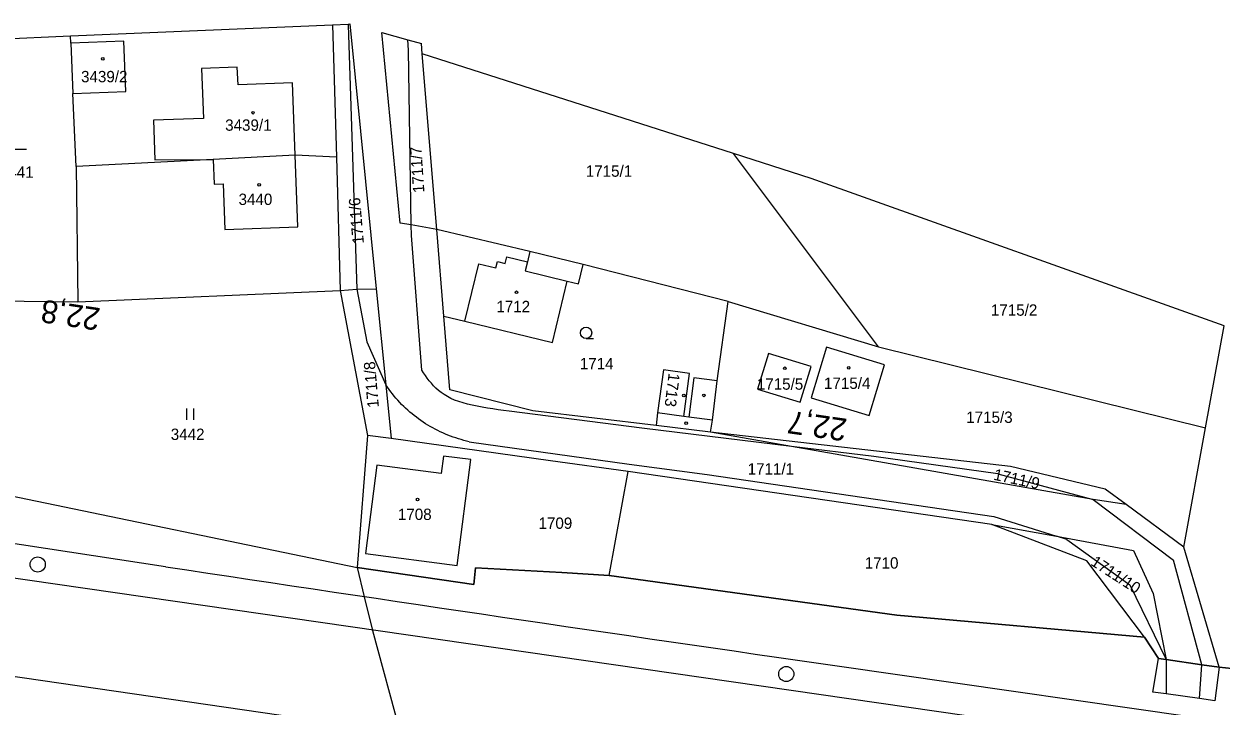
# Model space of a CAD drawing. Extents: x -757909 to -757266, y -1060303 to -1059942.
# Drawn here: x -757684 to -757525.7, y -1060142.5 to -1060052.3 of the extents above; entities that cross this region are included whole.
import ezdxf

# ---------------------------------------------------------------- set-up
doc = ezdxf.new("R2010")
doc.units = 0
for name, color, linetype in [('_hektaky', 7, 'Continuous'), ('_SO 102 hektometry', 7, 'Continuous'), ('Vrstva 1', 7, 'Continuous'), ('Vrstva 53', 7, 'Continuous'), ('Vrstva 55', 7, 'Continuous'), ('Vrstva 56', 7, 'Continuous'), ('Vrstva 57', 7, 'Continuous'), ('Vrstva 58', 7, 'Continuous'), ('Vrstva 59', 7, 'Continuous')]:
    doc.layers.add(name, color=color, linetype=linetype)

msp = doc.modelspace()

# ---------------------------------------------------------------- linework, layer by layer
at = {"layer": '_SO 102 hektometry'}
for centre in [(-757682.17, -1060123.76), (-757583.22, -1060138.24)]:
    msp.add_circle(centre, 1, dxfattribs=at)
at = {"layer": 'Vrstva 1'}
for p, q in [((-757429.32, -1060162.53), (-757720.62, -1060120.47)), ((-757665.26, -1060124.05), (-757689.98, -1060120.32)), ((-757576.18, -1060137.2), (-757470.2, -1060152.45))]:
    msp.add_line(p, q, dxfattribs=at)
msp.add_arc((-755796.09, -1047764.6), 12500, 261.400126, 261.812855, dxfattribs=at)
at = {"layer": 'Vrstva 53'}
for points in [[(-757852.31, -1060089.26), (-757789.66, -1060098.89), (-757785.7, -1060099.48), (-757730.83, -1060107.66), (-757729.12, -1060107.89), (-757699.16, -1060111.9), (-757687.19, -1060114.38), (-757639.93, -1060124.17), (-757624.54, -1060126.42), (-757624.32, -1060124.22), (-757612.89, -1060124.84), (-757606.63, -1060125.23), (-757568.62, -1060130.44), (-757535.86, -1060133.35), (-757534.03, -1060136.19), (-757533.01, -1060136.32), (-757528.28, -1060137.03), (-757525.99, -1060137.35), (-757523.49, -1060137.59)], [(-757328.56, -1060183.46), (-757338.29, -1060184.85), (-757361.91, -1060181.63), (-757443.58, -1060171.99), (-757470.38, -1060167.04), (-757513.1, -1060164.5), (-757526.21, -1060162.71), (-757533.6, -1060161.43), (-757535.01, -1060161.18), (-757542.9, -1060160.49), (-757543.88, -1060160.4), (-757632.1, -1060146.3), (-757634.26, -1060145.96), (-757635.44, -1060145.86), (-757686.64, -1060138.39), (-757693.18, -1060137.43), (-757732.62, -1060131.67), (-757793.56, -1060122.78), (-757866, -1060118.97)]]:
    msp.add_lwpolyline(points, dxfattribs=at)
at = {"layer": 'Vrstva 55'}
for p, q in [((-757677.84, -1060053.89), (-757643.18, -1060052.41)), ((-757643.18, -1060052.41), (-757642.66, -1060069.92)), ((-757643.18, -1060052.41), (-757642.66, -1060069.92)), ((-757640.91, -1060052.31), (-757637.42, -1060087.32)), ((-757688.39, -1060054.34), (-757677.84, -1060053.89)), ((-757677.8, -1060054.85), (-757677.84, -1060053.89)), ((-757677.8, -1060054.85), (-757677.51, -1060061.51)), ((-757631.34, -1060056.24), (-757631.45, -1060054.91)), ((-757629.39, -1060079.46), (-757631.34, -1060056.24)), ((-757590.19, -1060069.45), (-757631.34, -1060056.24)), ((-757677.1, -1060071.14), (-757677.51, -1060061.51)), ((-757571.04, -1060094.99), (-757590.19, -1060069.45)), ((-757579.91, -1060072.75), (-757590.19, -1060069.45)), ((-757677.1, -1060071.14), (-757676.88, -1060089.06)), ((-757642.66, -1060069.92), (-757642.17, -1060087.53)), ((-757642.66, -1060069.92), (-757642.17, -1060087.53)), ((-757525.35, -1060092.2), (-757579.91, -1060072.75)), ((-757628.47, -1060090.94), (-757629.39, -1060079.46)), ((-757590.9, -1060088.98), (-757610.05, -1060084.09)), ((-757676.88, -1060089.06), (-757642.17, -1060087.53)), ((-757642.17, -1060087.53), (-757638.59, -1060106.69)), ((-757642.17, -1060087.53), (-757638.59, -1060106.69)), ((-757689.45, -1060088.87), (-757676.88, -1060089.06)), ((-757592.34, -1060099.49), (-757590.9, -1060088.98)), ((-757590.9, -1060088.98), (-757571.04, -1060094.99)), ((-757527.8, -1060105.72), (-757525.35, -1060092.2)), ((-757571.04, -1060094.99), (-757527.8, -1060105.72)), ((-757592.99, -1060104.69), (-757592.34, -1060099.49)), ((-757593.23, -1060106.29), (-757600.41, -1060105.4)), ((-757593.23, -1060106.29), (-757592.99, -1060104.69)), ((-757530.66, -1060121.48), (-757527.8, -1060105.72)), ((-757638.59, -1060106.69), (-757639.93, -1060124.17)), ((-757638.59, -1060106.69), (-757639.93, -1060124.17)), ((-757635.45, -1060107.13), (-757638.59, -1060106.69)), ((-757606.63, -1060125.23), (-757604.11, -1060111.45)), ((-757556.06, -1060118.47), (-757604.11, -1060111.45)), ((-757687.19, -1060114.38), (-757639.93, -1060124.17)), ((-757530.66, -1060121.48), (-757538.3, -1060115.83)), ((-757525.99, -1060137.35), (-757530.66, -1060121.48))]:
    msp.add_line(p, q, dxfattribs=at)
for points in [[(-757643.18, -1060052.41), (-757641.12, -1060052.32), (-757640.91, -1060052.31)], [(-757643.18, -1060052.41), (-757642.66, -1060069.92), (-757642.17, -1060087.53), (-757638.59, -1060106.69), (-757639.93, -1060124.17), (-757639.03, -1060128.02), (-757637.9, -1060132.49), (-757634.26, -1060145.96), (-757630.94, -1060158.73), (-757631.18, -1060185.19), (-757631.2, -1060187.35)], [(-757629.39, -1060079.46), (-757632.79, -1060078.88), (-757634.26, -1060078.63), (-757636.66, -1060053.43), (-757633.26, -1060054.4), (-757631.45, -1060054.91)], [(-757677.51, -1060061.51), (-757670.5, -1060061.23), (-757670.77, -1060054.6), (-757677.8, -1060054.85)], [(-757642.66, -1060069.92), (-757648.14, -1060069.67), (-757658.97, -1060070.25), (-757677.1, -1060071.14)], [(-757610.05, -1060084.09), (-757617.11, -1060082.38), (-757629.39, -1060079.46)], [(-757628.47, -1060090.94), (-757625.72, -1060091.6), (-757614.14, -1060094.41), (-757612.17, -1060086.29), (-757610.67, -1060086.66), (-757610.05, -1060084.09)], [(-757642.17, -1060087.53), (-757639.97, -1060087.39), (-757637.42, -1060087.32)], [(-757637.42, -1060087.32), (-757636.16, -1060100.03), (-757635.45, -1060107.13)], [(-757600.41, -1060105.4), (-757616.74, -1060103.46), (-757627.69, -1060100.66), (-757628.47, -1060090.94)], [(-757579.94, -1060101.75), (-757572.27, -1060104.08), (-757570.24, -1060097.38), (-757577.88, -1060095.03), (-757579.94, -1060101.75)], [(-757581.36, -1060102.3), (-757579.91, -1060097.6), (-757585.56, -1060095.88), (-757587.03, -1060100.59), (-757581.36, -1060102.3)], [(-757592.34, -1060099.49), (-757595.44, -1060099.1), (-757596.09, -1060104.3), (-757596.77, -1060104.18), (-757595.99, -1060098.5), (-757599.43, -1060098.03), (-757600.22, -1060103.7), (-757600.41, -1060105.4)], [(-757604.11, -1060111.45), (-757614.37, -1060110.07), (-757635.45, -1060107.13)], [(-757538.3, -1060115.83), (-757542.65, -1060115.17), (-757582.51, -1060108.15), (-757593.23, -1060106.29)], [(-757538.3, -1060115.83), (-757541.05, -1060113.79), (-757553.6, -1060110.8), (-757593.23, -1060106.29)], [(-757637.32, -1060110.63), (-757638.83, -1060122.33), (-757626.73, -1060123.9), (-757624.93, -1060109.9), (-757628.52, -1060109.44), (-757628.82, -1060111.73), (-757637.32, -1060110.63)], [(-757535.86, -1060133.35), (-757543.49, -1060123.29), (-757556.06, -1060118.47)], [(-757556.06, -1060118.47), (-757547.51, -1060120.04), (-757537.32, -1060121.92), (-757534.73, -1060127.58), (-757533.01, -1060136.32)], [(-757606.63, -1060125.23), (-757612.89, -1060124.84), (-757624.32, -1060124.22), (-757624.54, -1060126.42), (-757639.93, -1060124.17)], [(-757639.93, -1060124.17), (-757639.03, -1060128.02), (-757637.9, -1060132.49), (-757634.26, -1060145.96)], [(-757639.93, -1060124.17), (-757639.03, -1060128.02), (-757637.9, -1060132.49), (-757634.26, -1060145.96)], [(-757535.86, -1060133.35), (-757568.62, -1060130.44), (-757606.63, -1060125.23)], [(-757533.01, -1060136.32), (-757534.03, -1060136.19), (-757535.86, -1060133.35)], [(-757525.99, -1060137.35), (-757528.28, -1060137.03), (-757533.01, -1060136.32)], [(-757515.4, -1060138.37), (-757518.94, -1060138.03), (-757520.85, -1060137.84), (-757523.49, -1060137.59), (-757525.99, -1060137.35)], [(-757634.26, -1060145.96), (-757635.44, -1060145.86), (-757686.64, -1060138.39)]]:
    msp.add_lwpolyline(points, dxfattribs=at)
at = {"layer": 'Vrstva 56'}
for p, q in [((-757641.12, -1060052.42), (-757641.12, -1060052.32)), ((-757641.12, -1060052.42), (-757639.97, -1060087.39)), ((-757633.15, -1060055.76), (-757633.26, -1060054.4)), ((-757632.79, -1060078.88), (-757633.15, -1060055.76)), ((-757655.79, -1060058.03), (-757660.5, -1060058.19)), ((-757660.5, -1060058.19), (-757660.27, -1060064.81)), ((-757655.69, -1060060.37), (-757655.79, -1060058.03)), ((-757648.49, -1060060.1), (-757655.69, -1060060.37)), ((-757648.14, -1060069.67), (-757648.49, -1060060.1)), ((-757660.27, -1060064.81), (-757666.88, -1060065.04)), ((-757666.88, -1060065.04), (-757666.7, -1060070.26)), ((-757647.79, -1060079.11), (-757648.14, -1060069.67)), ((-757666.7, -1060070.26), (-757658.97, -1060070.25)), ((-757658.97, -1060070.25), (-757658.85, -1060073.5)), ((-757658.85, -1060073.5), (-757657.65, -1060073.45)), ((-757657.65, -1060073.45), (-757657.42, -1060079.47)), ((-757657.42, -1060079.47), (-757647.79, -1060079.11)), ((-757632.77, -1060080.29), (-757632.79, -1060078.88)), ((-757631.4, -1060098.08), (-757632.77, -1060080.29)), ((-757617.11, -1060082.38), (-757617.44, -1060083.74)), ((-757625.72, -1060091.6), (-757623.88, -1060084)), ((-757623.88, -1060084), (-757621.6, -1060084.55)), ((-757621.6, -1060084.55), (-757621.4, -1060083.71)), ((-757621.4, -1060083.71), (-757620.38, -1060083.96)), ((-757620.38, -1060083.96), (-757620.16, -1060083.08)), ((-757620.16, -1060083.08), (-757617.44, -1060083.74)), ((-757617.44, -1060083.74), (-757617.73, -1060084.95)), ((-757617.73, -1060084.95), (-757612.17, -1060086.29)), ((-757639.97, -1060087.39), (-757638.66, -1060094.33)), ((-757638.66, -1060094.33), (-757636.16, -1060100.03)), ((-757602.33, -1060105.73), (-757619.86, -1060103.51)), ((-757596.77, -1060104.18), (-757600.22, -1060103.7)), ((-757592.99, -1060104.69), (-757596.09, -1060104.3)), ((-757582.51, -1060108.15), (-757602.33, -1060105.73)), ((-757625.12, -1060107.53), (-757604, -1060110.48)), ((-757571.64, -1060109.48), (-757582.51, -1060108.15)), ((-757604, -1060110.48), (-757593.68, -1060111.85)), ((-757555.27, -1060111.76), (-757571.64, -1060109.48)), ((-757593.68, -1060111.85), (-757555.79, -1060117.41)), ((-757555.27, -1060111.76), (-757542.65, -1060115.17)), ((-757542.65, -1060115.17), (-757532.02, -1060123.21)), ((-757555.79, -1060117.41), (-757547.51, -1060120.04)), ((-757546.14, -1060120.48), (-757547.51, -1060120.04)), ((-757546.14, -1060120.48), (-757537.81, -1060126.43)), ((-757528.28, -1060137.03), (-757532.02, -1060123.21)), ((-757537.81, -1060126.43), (-757533.01, -1060136.32)), ((-757534.76, -1060140.62), (-757534.03, -1060136.19)), ((-757533.01, -1060136.32), (-757532.98, -1060140.88)), ((-757528.61, -1060141.49), (-757528.28, -1060137.03)), ((-757525.99, -1060137.35), (-757526.57, -1060141.77)), ((-757532.98, -1060140.88), (-757534.76, -1060140.62)), ((-757528.61, -1060141.49), (-757532.98, -1060140.88)), ((-757526.57, -1060141.77), (-757528.61, -1060141.49))]:
    msp.add_line(p, q, dxfattribs=at)
for points in [[(-757619.86, -1060103.51), (-757620.58, -1060103.41), (-757621.3, -1060103.31), (-757622.01, -1060103.2), (-757622.71, -1060103.09), (-757623.4, -1060102.97), (-757624.07, -1060102.84), (-757624.72, -1060102.71), (-757625.35, -1060102.55), (-757625.95, -1060102.39), (-757626.52, -1060102.21), (-757627.06, -1060102.02), (-757627.56, -1060101.8), (-757628.02, -1060101.56), (-757628.45, -1060101.31), (-757628.84, -1060101.03), (-757629.2, -1060100.75), (-757629.53, -1060100.44), (-757629.84, -1060100.13), (-757630.13, -1060099.8), (-757630.41, -1060099.47), (-757630.67, -1060099.13), (-757630.92, -1060098.78), (-757631.16, -1060098.43), (-757631.4, -1060098.08)], [(-757625.12, -1060107.53), (-757625.48, -1060107.45), (-757625.84, -1060107.36), (-757626.2, -1060107.26), (-757626.55, -1060107.15), (-757626.9, -1060107.04), (-757627.25, -1060106.92), (-757627.6, -1060106.79), (-757627.94, -1060106.66), (-757628.28, -1060106.52), (-757628.62, -1060106.37), (-757628.96, -1060106.22), (-757629.29, -1060106.06), (-757629.62, -1060105.89), (-757629.95, -1060105.71), (-757630.27, -1060105.53), (-757630.58, -1060105.34), (-757630.9, -1060105.15), (-757631.21, -1060104.95), (-757631.51, -1060104.74), (-757631.82, -1060104.52), (-757632.11, -1060104.3), (-757632.41, -1060104.08), (-757632.69, -1060103.85), (-757632.97, -1060103.61), (-757633.25, -1060103.36), (-757633.53, -1060103.11), (-757633.79, -1060102.86), (-757634.06, -1060102.6), (-757634.31, -1060102.33), (-757634.56, -1060102.06), (-757634.81, -1060101.79), (-757635.05, -1060101.51), (-757635.28, -1060101.22), (-757635.51, -1060100.93), (-757635.73, -1060100.63), (-757635.95, -1060100.33), (-757636.16, -1060100.03)]]:
    msp.add_lwpolyline(points, dxfattribs=at)
at = {"layer": 'Vrstva 58'}
for p, q in [((-757685.65, -1060068.88), (-757683.65, -1060068.88)), ((-757609.69, -1060093.89), (-757608.69, -1060093.89)), ((-757662.51, -1060103.14), (-757662.51, -1060104.64)), ((-757661.51, -1060104.64), (-757661.51, -1060103.14))]:
    msp.add_line(p, q, dxfattribs=at)
msp.add_circle((-757609.69, -1060093.14), 0.75, dxfattribs=at)
at = {"layer": 'Vrstva 59'}
for centre in [(-757673.58, -1060056.91), (-757653.71, -1060064.04), (-757652.89, -1060073.57), (-757618.88, -1060087.78), (-757583.42, -1060097.83), (-757574.97, -1060097.77), (-757596.74, -1060101.43), (-757594.1, -1060101.41), (-757596.44, -1060105.07), (-757631.95, -1060115.17)]:
    msp.add_circle(centre, 0.175, dxfattribs=at)

# ---------------------------------------------------------------- texts
at = {"layer": '_hektaky'}
for s, rotation, p in [('22,8', 171.4001, (-757673.76, -1060089.9)), ('22,7', 171.7816, (-757575.06, -1060104.53))]:
    msp.add_text(s, height=3, rotation=rotation, dxfattribs=at).set_placement(p)
at = {"layer": 'Vrstva 57'}
for s, p in [('3439/2', (-757676.44, -1060060.02)), ('3439/1', (-757657.39, -1060066.43)), ('3441', (-757687.17, -1060072.64)), ('1715/1', (-757609.72, -1060072.51)), ('3440', (-757655.62, -1060076.24)), ('1712', (-757621.54, -1060090.41)), ('1715/2', (-757556.17, -1060090.88)), ('1714', (-757610.51, -1060097.96)), ('1715/5', (-757587.11, -1060100.66)), ('1715/4', (-757578.23, -1060100.55)), ('1715/3', (-757559.43, -1060105.05)), ('3442', (-757664.58, -1060107.3)), ('1711/1', (-757588.32, -1060111.87)), ('1708', (-757634.56, -1060117.88)), ('1709', (-757615.97, -1060119.05)), ('1710', (-757572.85, -1060124.31))]:
    msp.add_text(s, height=1.5, dxfattribs=at).set_placement(p)
for s, rotation, p in [('1711/7', 94, (-757631.04, -1060074.59)), ('1711/6', 95, (-757639.04, -1060081.32)), ('1711/8', 95, (-757637.06, -1060102.98)), ('1713', 263, (-757598.76, -1060098.4)), ('1711/9', 348, (-757555.9, -1060112.55)), ('1711/10', 327, (-757543.09, -1060123.76))]:
    msp.add_text(s, height=1.5, rotation=rotation, dxfattribs=at).set_placement(p)

doc.saveas('drawing.dxf')
